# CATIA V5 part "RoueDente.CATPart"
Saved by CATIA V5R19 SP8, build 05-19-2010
Part number: pignon
Source: Unknown
Publications: "Esquisse.8", "Plan.3"
Material "Rouge DS": density 7860 kg/m3, Young's modulus 2e+11 Pa, Poisson ratio 0.266
Bounding box of the stored display mesh (mm): x -10 to 5, y -22.496 to 22.496, z -22.466 to 22.496
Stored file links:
  E:\EDELI\gcausse\Edeli_2012_233_gcausse\RoueDente.CATPart
  C:\usr\gt1\projet\site_web\doc\catia\gears\spur_gear_files\parts\gear_n.CATPart
  C:\Users\thinkmotion1\Desktop\Nouveau dossier\Cremai_Automobile\Cremaillere_automobile.CATProduct
  C:\Program Files\Dassault Systemes\B20\win_b64\startup\materials\French\Catalog.CATMaterial
  C:\Program Files\Dassault Systemes\B20\win_b64\startup\materials\red_env_512x512.jpg
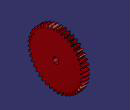
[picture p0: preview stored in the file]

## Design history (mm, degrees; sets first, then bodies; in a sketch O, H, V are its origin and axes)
Parameters
  a = 20 deg
  m = 1 mm
  Z = 43
  rp = 21.5 mm {= m * Z / 2}
  ra = 22.5 mm {= rp + m}
  rb = 20.2034 mm {= rp * cos( a )}
  rf = 20.25 mm {= rp - 1.25 * m}
  rc = 0.38 mm {= m * 0.38}
  c = 0.115855 {= sqrt( 1 / ( cos( a ) * cos( a ) ) - 1 ) / PI}
  phi = 2.947 deg
  `diametre perçages extérieurs` = 35 mm
Set1
  DatumCurve1: linked copy from another document
Set2
  Line1 "Axe X": stored without definition
  Plane1: type Angle, RefPlane zx-plane, Direction Line1, Angle 4.186 {= 180deg / Z}
  Point1 "origine": (0, 0, 0)
  Point2: (0, 0, 20.2034)
  Point3: (0, 0.2068, 21.1759)
  Point4: (0, 1.6055, 23.8063)
  Point5: (0, 5.1527, 27.2799)
  Point6: (0, 11.3691, 30.3889)
  Curve1: Elements (Point2; Point3; Point4; Point5; Point6)
  Extrapol1: ToExtrapol Point2, Support Curve1, Length 2 {= m * 2}
  Rotate1: ToTransfor Extrapol1, Axis Line1, Angle 2.947 {= phi}
  Circle1: type CtrRad, Start 0, End 180, Center Point1, Support yz-plane, Radius 20.25 {= rf}, FirstDirection (0, 1, 0)
  Circle2: type CtrRad, Start 0, End 180, Center Point1, Support yz-plane, Radius 22.5 {= ra}, FirstDirection (0, 1, 0)
  Corner1: Element1 Rotate1, Element2 Circle1, Radius 0.38 {= rc}
  Symmetry1: ToTransfor Corner1, Reference Plane1
  Split1: ToCut Rotate1, Cutting (Corner1; Circle2)
  Symmetry2: ToTransfor Split1, Reference zx-plane
  Circle3: type 2PointsRad, Start 0, End 180, FirstPoint vertex of Symmetry1, SecondPoint vertex of Corner1, Support yz-plane, Radius 20.25 {= rf}
  Circle4: type 2PointsRad, Start 0, End 180, FirstPoint vertex of Split1, SecondPoint vertex of Symmetry2, Support yz-plane, Radius 22.5 {= ra}
  Join1: Elements (Symmetry1; Circle3; Corner1; Split1; Circle4; Symmetry2)
  CircPattern1: of Join1, instances 43 {= Z}, angular step 8.3721 {= 360.0*1 deg/CircPattern1.AngularNumber}, axis from Line1
  Join2: Elements (Join1; CircPattern1)
  Plane2: type Offset, RefPlane yz-plane, Offset 33
  Sketch1 on start face of Pad1, origin (0, 0, 0), H (0, -1, 0), V (0, 0, 1)
    circle A1 centre (0, 0) radius 2.5
    radius A1 = 2.5
Body1 (main body)
  Pad1: profile Join2, length 5
  Sketch2 on Plane2, origin (33, 0, 0), H (0, 1, 0), V (0, 0, 1)
    circle A1 centre (0, 0) radius 31.6677
    radius A1 = 31.6677
  Sketch3 on start face of Pad1, origin (0, 0, 0), H (0, -1, 0), V (0, 0, 1)
    circle A1 centre (0, 0) radius 10
    radius A1 = 10
  Sketch4 on end face of Pad1, origin (5, 0, 0), H (0, 1, 0), V (0, 0, 1)
    circle A1 centre (0, 0) radius 10
    radius A1 = 10
  Pocket1: profile Sketch1, direction (1, 0, 0), length 30
  Sketch5 on start face of Pad1, origin (0, 0, 0), H (0, -1, 0), V (0, 0, 1)
    circle A1 centre (15, 0) radius 2.5
    point P1 (15, 0)
    radius A1 = 2.5
    distance O P1 = 15
    coincidence: P1 H
  Pad2: profile Sketch5, direction (-1, 0, 0), length 10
